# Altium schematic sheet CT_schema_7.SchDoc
size 298 x 271 mm
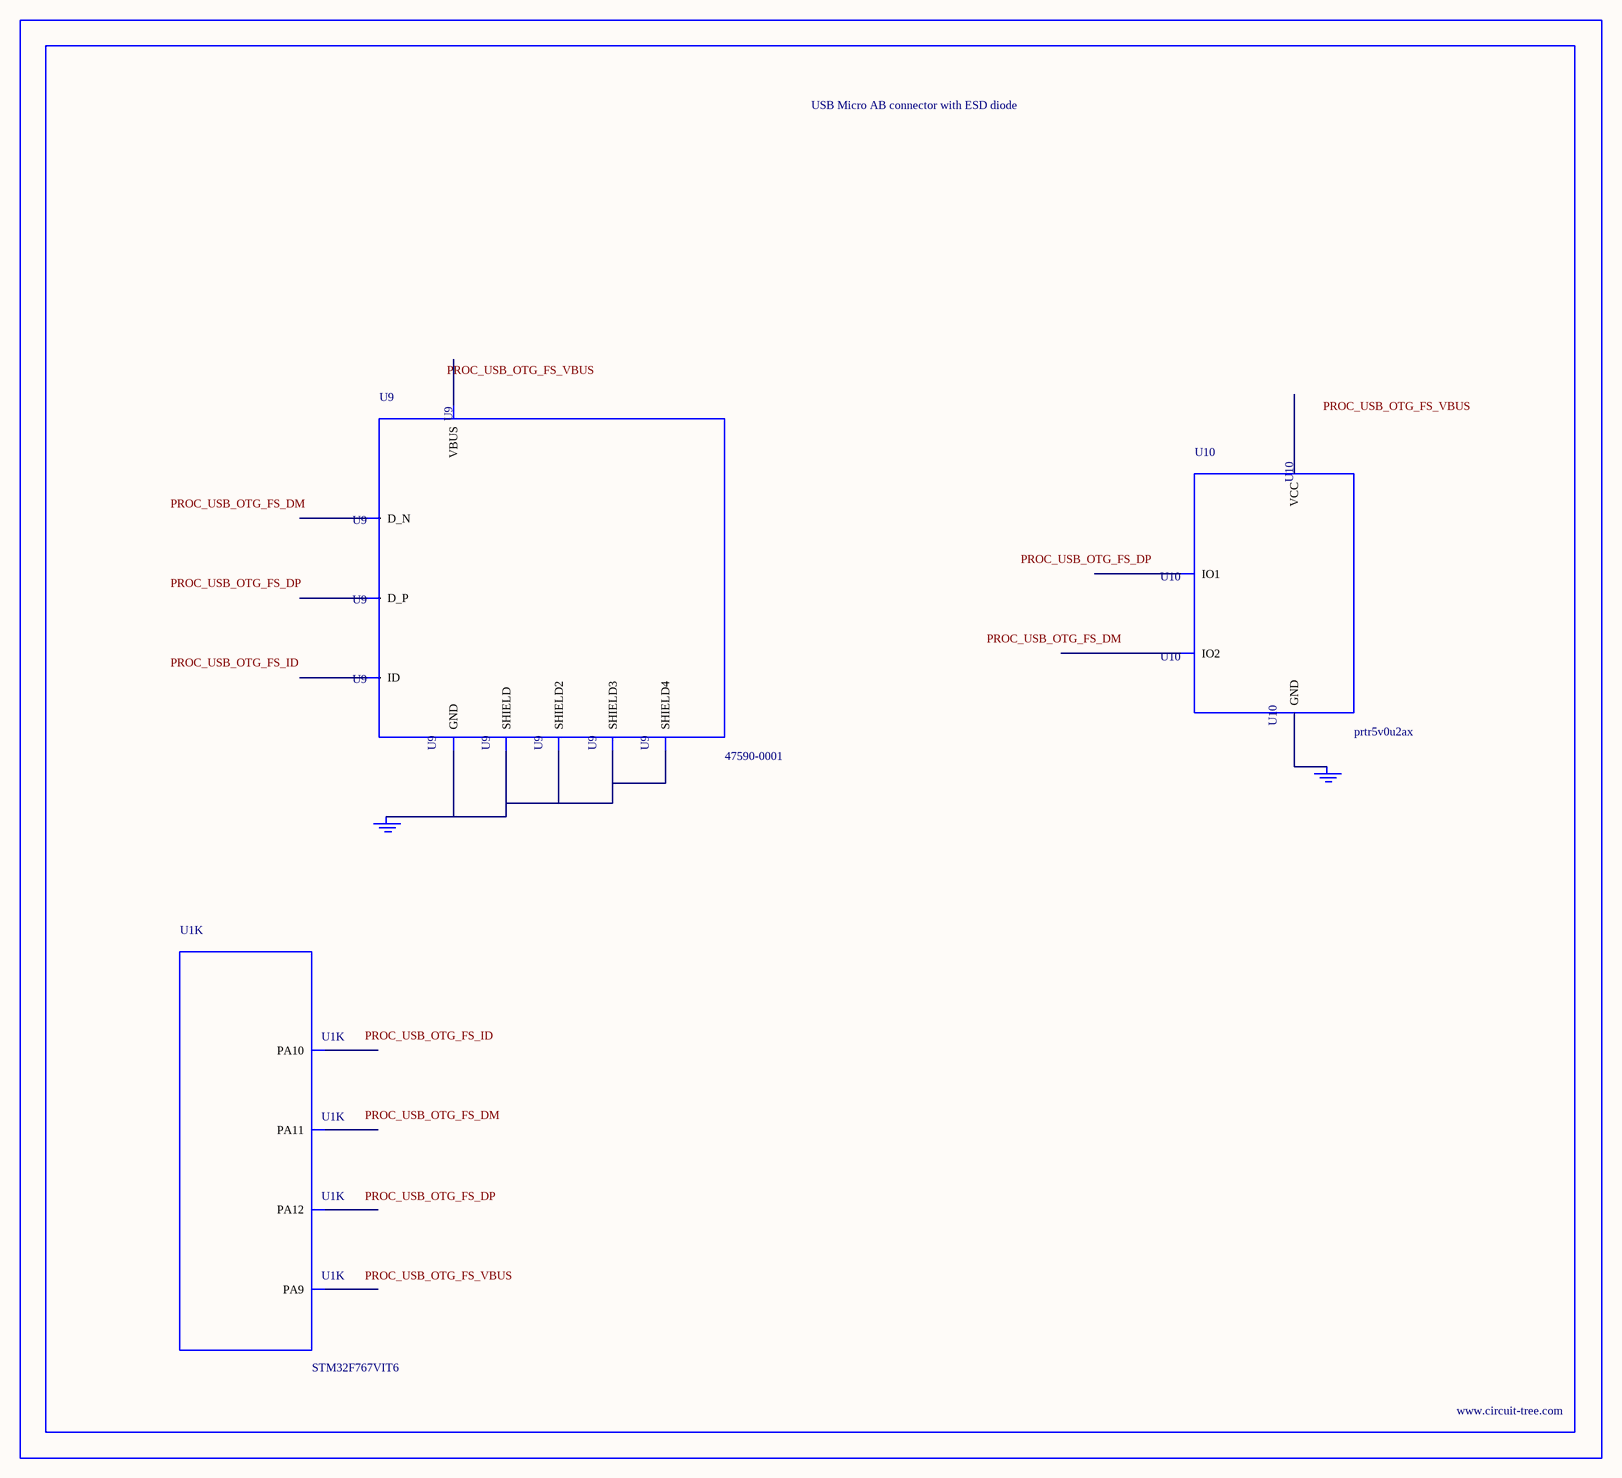
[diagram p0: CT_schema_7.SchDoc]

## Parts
BORDER6  (no value)
GND_INSTANCE_6_0  (no value)
GND_INSTANCE_6_1  (no value)
U1  STM32F767VIT6  [LQFP100]  (part K of 11)
U9  47590-0001  [MICRO_USB_AB]
U10  prtr5v0u2ax  [SOT143B]

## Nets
NetGND_INSTANCE_6_0_0: GND_INSTANCE_6_0.0(GND) U9.5(GND) U9.6(SHIELD) U9.7(SHIELD2) U9.8(SHIELD3) U9.9(SHIELD4)
NetGND_INSTANCE_6_1_0: GND_INSTANCE_6_1.0(GND) U10.1(GND)

Not connected (* = marked no-connect by the designer): U1 68(PA9) 69(PA10) 70(PA11) 71(PA12); U9 1(VBUS) 2(D_N) 3(D_P) 4(ID); U10 2(IO1) 3(IO2) 4(VCC)

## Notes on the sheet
- Labels drawn without touching a wire or pin: PROC_USB_OTG_FS_DM, PROC_USB_OTG_FS_DP, PROC_USB_OTG_FS_ID, PROC_USB_OTG_FS_VBUS

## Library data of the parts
BORDER6 = BORDER_PAGE6
GND_INSTANCE_6_0 GND_INSTANCE_6_1 = GND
